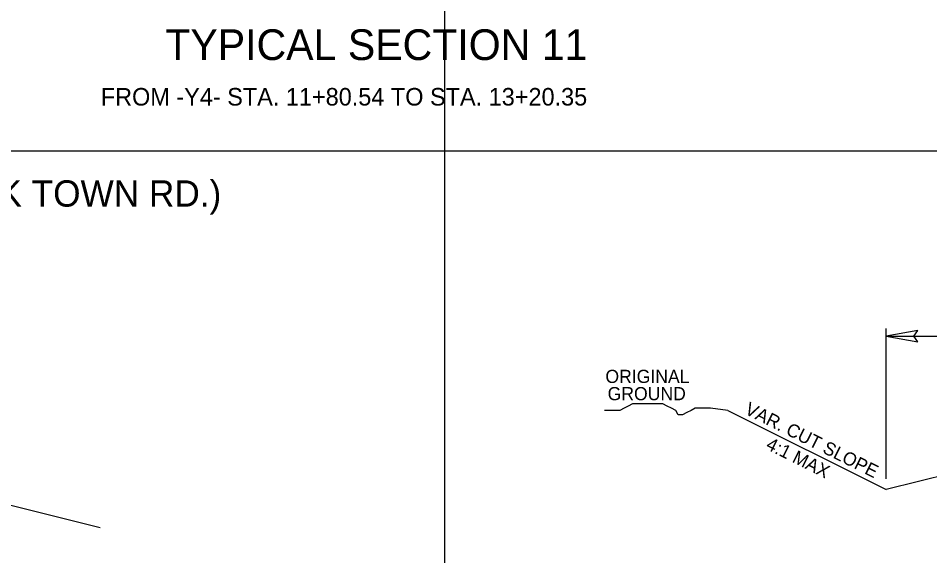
# Model space of a CAD drawing. Extents: x 1487909 to 1489267, y 497866 to 499814.
# Drawn here: x 1488950.7 to 1489002.6, y 497915.6 to 497946.3 of the extents above; entities that cross this region are included whole.
import ezdxf

# ---------------------------------------------------------------- set-up
doc = ezdxf.new("R2010")
doc.units = 0
for name, color, linetype in [('Exist XS Ground Line', 7, 'Continuous'), ('Prop Dimension', 7, 'Continuous'), ('Prop Terminator CELL', 7, 'Continuous'), ('Scratch_Level_1', 7, 'Continuous'), ('Typical Hinge Slope Arterial CELL', 7, 'Continuous'), ('Typical Hinge Slope Interstate CELL', 7, 'Continuous'), ('Typical Pavement Slope CELL', 7, 'Continuous')]:
    doc.layers.add(name, color=color, linetype=linetype)

msp = doc.modelspace()

# ---------------------------------------------------------------- linework, layer by layer
at = {"layer": 'Exist XS Ground Line'}
msp.add_line((1488949.329, 497918.75), (1488955.329, 497917.25), dxfattribs=at)
at = {"layer": 'Prop Dimension'}
for p, q in [((1489000.127, 497920.026), (1489000.127, 497928.598)), ((1489000.127, 497928.159), (1489008.127, 497928.159))]:
    msp.add_line(p, q, dxfattribs=at)
at = {"layer": 'Prop Terminator CELL'}
msp.add_lwpolyline([(1489001.927, 497928.469), (1489000.127, 497928.159), (1489001.937, 497927.839), (1489001.707, 497928.159)], close=True, dxfattribs=at)
at = {"layer": 'Scratch_Level_1'}
for p, q in [((1488974.964, 497868.721), (1488974.964, 497973.721)), ((1488899.964, 497938.721), (1489049.964, 497938.721))]:
    msp.add_line(p, q, dxfattribs=at)
at = {"layer": 'Typical Hinge Slope Arterial CELL'}
for p in [(1488991.098, 497923.924), (1489008.127, 497921.41)]:
    msp.add_line(p, (1489000.127, 497919.41), dxfattribs=at)
msp.add_lwpolyline([(1488991.098, 497923.924), (1488990.112, 497924.047), (1488989.866, 497924.047), (1488989.496, 497924.047), (1488989.249, 497924.047), (1488989.003, 497923.924), (1488988.757, 497923.8), (1488988.51, 497923.677), (1488988.264, 497923.677), (1488988.14, 497923.924), (1488987.894, 497924.047), (1488987.648, 497924.171), (1488987.401, 497924.293), (1488987.155, 497924.293), (1488986.908, 497924.293), (1488986.662, 497924.293), (1488986.416, 497924.293), (1488986.169, 497924.293), (1488985.923, 497924.293), (1488985.677, 497924.293), (1488985.43, 497924.171), (1488985.184, 497924.047), (1488984.938, 497923.924), (1488984.568, 497923.924), (1488984.321, 497923.924), (1488984.075, 497923.924)], dxfattribs=at)

# ---------------------------------------------------------------- texts
for s, height, p in [('FROM -Y4- STA. 11+80.54 TO STA. 13+20.35', 1, (1488955.363, 497941.296)), ('ORIGINAL', 0.75, (1488984.124, 497925.488)), ('GROUND', 0.75, (1488984.25, 497924.505))]:
    msp.add_text(s, height=height, dxfattribs=at).set_placement(p)
for s, p in [('VAR. CUT SLOPE', (1488992.009, 497923.758)), ('4:1 MAX', (1488993.221, 497921.756))]:
    msp.add_text(s, height=0.75, rotation=333.4658, dxfattribs=at).set_placement(p)
at = {"layer": 'Typical Hinge Slope Interstate CELL'}
msp.add_text('C -Y4- (TANK TOWN RD.)', height=1.5, dxfattribs=at).set_placement((1488938.498, 497935.534))
at = {"layer": 'Typical Pavement Slope CELL'}
msp.add_text('TYPICAL SECTION 11', height=1.75, dxfattribs=at).set_placement((1488959.04, 497943.888))

doc.saveas('drawing.dxf')
